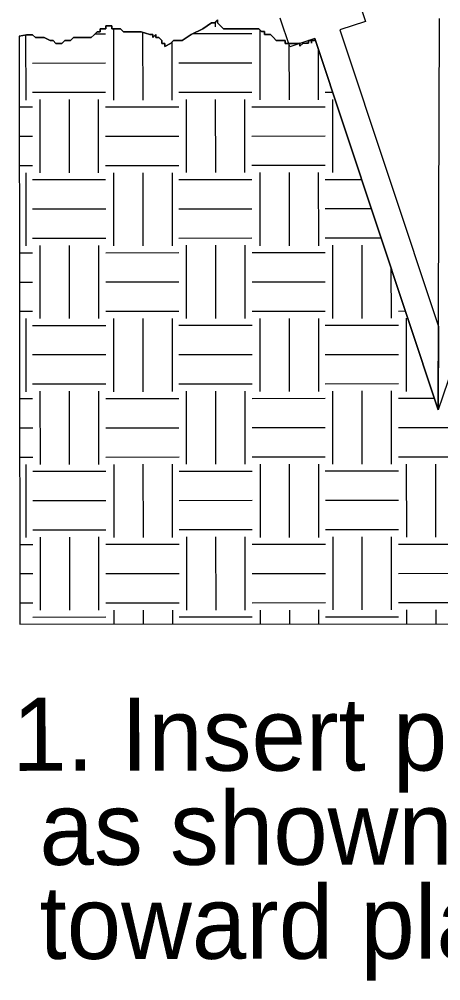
# Model space of a CAD drawing. Extents: x 1728110 to 1729925, y 1284214 to 1285339.
# Drawn here: x 1728642.1 to 1728681.8, y 1284892.4 to 1284982.9 of the extents above; entities that cross this region are included whole.
import ezdxf

# ---------------------------------------------------------------- set-up
doc = ezdxf.new("R2010")
doc.units = 0
doc.layers.add('Reforestation Detail CELL', color=7, linetype='Continuous')

msp = doc.modelspace()

# ---------------------------------------------------------------- linework, layer by layer
at = {"layer": 'Reforestation Detail CELL'}
for p, q in [((1728673.847, 1284985.427), (1728674.742, 1284982.732)), ((1728660.594, 1284982.672), (1728660.595, 1284982.231)), ((1728667.607, 1284980.362), (1728666.712, 1284983.056)), ((1728674.742, 1284982.732), (1728672.342, 1284981.935)), ((1728681.587, 1284946.157), (1728681.712, 1284983.026)), ((1728642.733, 1284981.47), (1728642.738, 1284975.328)), ((1728649.278, 1284981.582), (1728650.26, 1284981.582)), ((1728651, 1284982.048), (1728651.005, 1284975.334)), ((1728653.757, 1284981.727), (1728653.761, 1284975.336)), ((1728658.496, 1284981.589), (1728664.04, 1284981.592)), ((1728664.78, 1284981.962), (1728664.785, 1284975.345)), ((1728672.342, 1284981.935), (1728681.614, 1284954.007)), ((1728642.131, 1284981.35), (1728642.174, 1284925.976)), ((1728656.513, 1284980.797), (1728656.517, 1284975.338)), ((1728667.537, 1284980.677), (1728667.541, 1284975.346)), ((1728669.97, 1284981.148), (1728667.607, 1284980.362)), ((1728681.587, 1284946.157), (1728669.97, 1284981.148)), ((1728669.97, 1284981.148), (1728681.587, 1284946.157)), ((1728681.587, 1284946.157), (1728669.97, 1284981.148)), ((1728670.293, 1284980.178), (1728670.297, 1284975.348)), ((1728643.373, 1284978.821), (1728650.262, 1284978.826)), ((1728657.153, 1284978.831), (1728664.042, 1284978.837)), ((1728643.375, 1284976.065), (1728650.264, 1284976.07)), ((1728657.154, 1284976.075), (1728664.044, 1284976.081)), ((1728670.934, 1284976.086), (1728671.651, 1284976.087)), ((1728644.064, 1284975.377), (1728644.069, 1284968.487)), ((1728646.82, 1284975.379), (1728646.825, 1284968.49)), ((1728649.576, 1284975.381), (1728649.581, 1284968.491)), ((1728657.844, 1284975.387), (1728657.849, 1284968.498)), ((1728660.6, 1284975.389), (1728660.605, 1284968.5)), ((1728663.356, 1284975.391), (1728663.361, 1284968.501)), ((1728671.624, 1284975.397), (1728671.629, 1284968.508)), ((1728642.137, 1284974.687), (1728643.376, 1284974.688)), ((1728650.266, 1284974.693), (1728657.156, 1284974.698)), ((1728664.045, 1284974.703), (1728670.935, 1284974.708)), ((1728642.139, 1284971.931), (1728643.378, 1284971.932)), ((1728650.267, 1284971.937), (1728657.158, 1284971.942)), ((1728664.047, 1284971.947), (1728670.937, 1284971.952)), ((1728642.141, 1284969.175), (1728643.38, 1284969.176)), ((1728650.27, 1284969.181), (1728657.16, 1284969.186)), ((1728664.049, 1284969.191), (1728670.939, 1284969.196)), ((1728642.743, 1284968.486), (1728642.747, 1284961.596)), ((1728643.381, 1284967.846), (1728650.271, 1284967.851)), ((1728651.011, 1284968.493), (1728651.015, 1284961.602)), ((1728653.766, 1284968.495), (1728653.771, 1284961.604)), ((1728656.522, 1284968.496), (1728656.527, 1284961.607)), ((1728657.16, 1284967.856), (1728664.05, 1284967.861)), ((1728664.79, 1284968.503), (1728664.795, 1284961.613)), ((1728667.546, 1284968.505), (1728667.551, 1284961.615)), ((1728670.302, 1284968.506), (1728670.307, 1284961.617)), ((1728670.94, 1284967.866), (1728674.379, 1284967.869)), ((1728643.383, 1284965.09), (1728650.273, 1284965.095)), ((1728657.163, 1284965.1), (1728664.052, 1284965.105)), ((1728670.942, 1284965.11), (1728675.293, 1284965.114)), ((1728643.385, 1284962.334), (1728650.275, 1284962.339)), ((1728644.075, 1284961.646), (1728644.079, 1284954.756)), ((1728646.83, 1284961.648), (1728646.835, 1284954.758)), ((1728649.586, 1284961.65), (1728649.591, 1284954.76)), ((1728657.165, 1284962.344), (1728664.054, 1284962.349)), ((1728657.854, 1284961.656), (1728657.859, 1284954.766)), ((1728660.61, 1284961.658), (1728660.615, 1284954.769)), ((1728663.366, 1284961.66), (1728663.371, 1284954.77)), ((1728670.944, 1284962.354), (1728676.209, 1284962.358)), ((1728671.634, 1284961.666), (1728671.639, 1284954.777)), ((1728674.39, 1284961.668), (1728674.395, 1284954.779)), ((1728642.147, 1284960.955), (1728643.387, 1284960.956)), ((1728650.276, 1284960.962), (1728657.166, 1284960.967)), ((1728664.056, 1284960.972), (1728670.945, 1284960.977)), ((1728677.147, 1284959.532), (1728677.151, 1284954.78)), ((1728642.15, 1284958.2), (1728643.388, 1284958.201)), ((1728650.278, 1284958.206), (1728657.168, 1284958.211)), ((1728664.057, 1284958.216), (1728670.948, 1284958.221)), ((1728642.151, 1284955.444), (1728643.39, 1284955.445)), ((1728650.28, 1284955.45), (1728657.17, 1284955.455)), ((1728664.059, 1284955.46), (1728670.949, 1284955.465)), ((1728677.839, 1284955.47), (1728678.495, 1284955.471)), ((1728642.753, 1284954.755), (1728642.758, 1284947.865)), ((1728651.02, 1284954.761), (1728651.026, 1284947.871)), ((1728653.777, 1284954.764), (1728653.782, 1284947.873)), ((1728656.533, 1284954.765), (1728656.537, 1284947.875)), ((1728664.8, 1284954.772), (1728664.805, 1284947.881)), ((1728667.556, 1284954.774), (1728667.561, 1284947.883)), ((1728670.312, 1284954.775), (1728670.317, 1284947.886)), ((1728678.58, 1284954.782), (1728678.585, 1284947.891)), ((1728643.392, 1284954.115), (1728650.281, 1284954.12)), ((1728657.171, 1284954.125), (1728664.061, 1284954.13)), ((1728670.95, 1284954.135), (1728677.84, 1284954.14)), ((1728681.614, 1284954.007), (1728681.587, 1284946.157)), ((1728684.111, 1284953.591), (1728681.587, 1284946.157)), ((1728684.111, 1284953.591), (1728681.587, 1284946.157)), ((1728643.393, 1284951.359), (1728650.283, 1284951.364)), ((1728657.173, 1284951.369), (1728664.062, 1284951.374)), ((1728670.953, 1284951.379), (1728677.842, 1284951.384)), ((1728643.395, 1284948.603), (1728650.286, 1284948.608)), ((1728657.175, 1284948.613), (1728664.064, 1284948.618)), ((1728660.62, 1284947.927), (1728660.625, 1284941.037)), ((1728663.376, 1284947.929), (1728663.381, 1284941.039)), ((1728670.955, 1284948.623), (1728677.844, 1284948.628)), ((1728671.644, 1284947.935), (1728671.649, 1284941.045)), ((1728674.4, 1284947.937), (1728674.405, 1284941.048)), ((1728677.156, 1284947.939), (1728677.161, 1284941.049)), ((1728642.158, 1284947.223), (1728643.397, 1284947.224)), ((1728644.085, 1284947.914), (1728644.09, 1284941.025)), ((1728646.841, 1284947.917), (1728646.846, 1284941.027)), ((1728649.597, 1284947.919), (1728649.601, 1284941.028)), ((1728650.286, 1284947.23), (1728657.176, 1284947.235)), ((1728657.864, 1284947.925), (1728657.869, 1284941.035)), ((1728664.066, 1284947.241), (1728670.955, 1284947.246)), ((1728677.845, 1284947.251), (1728681.223, 1284947.253)), ((1728642.16, 1284944.468), (1728643.398, 1284944.469)), ((1728650.289, 1284944.473), (1728657.178, 1284944.48)), ((1728664.068, 1284944.485), (1728670.958, 1284944.49)), ((1728677.847, 1284944.495), (1728684.737, 1284944.5)), ((1728642.161, 1284941.712), (1728643.4, 1284941.713)), ((1728650.291, 1284941.719), (1728657.18, 1284941.724)), ((1728664.07, 1284941.729), (1728670.96, 1284941.734)), ((1728677.849, 1284941.739), (1728684.739, 1284941.744)), ((1728642.763, 1284941.023), (1728642.769, 1284934.134)), ((1728651.031, 1284941.03), (1728651.036, 1284934.14)), ((1728653.787, 1284941.032), (1728653.792, 1284934.142)), ((1728656.543, 1284941.034), (1728656.548, 1284934.144)), ((1728664.81, 1284941.04), (1728664.816, 1284934.15)), ((1728667.567, 1284941.042), (1728667.571, 1284934.152)), ((1728670.322, 1284941.044), (1728670.328, 1284934.155)), ((1728678.59, 1284941.051), (1728678.595, 1284934.16)), ((1728681.346, 1284941.053), (1728681.351, 1284934.162)), ((1728643.402, 1284940.384), (1728650.291, 1284940.389)), ((1728657.182, 1284940.394), (1728664.071, 1284940.399)), ((1728670.96, 1284940.404), (1728677.85, 1284940.409)), ((1728643.404, 1284937.628), (1728650.294, 1284937.633)), ((1728657.183, 1284937.638), (1728664.073, 1284937.643)), ((1728670.963, 1284937.648), (1728677.852, 1284937.653)), ((1728643.406, 1284934.872), (1728650.296, 1284934.877)), ((1728657.185, 1284934.882), (1728664.075, 1284934.887)), ((1728670.965, 1284934.892), (1728677.854, 1284934.897)), ((1728642.168, 1284933.492), (1728643.407, 1284933.493)), ((1728644.095, 1284934.183), (1728644.101, 1284927.293)), ((1728646.851, 1284934.185), (1728646.857, 1284927.295)), ((1728649.607, 1284934.188), (1728649.612, 1284927.297)), ((1728650.296, 1284933.499), (1728657.186, 1284933.503)), ((1728657.874, 1284934.193), (1728657.88, 1284927.304)), ((1728660.631, 1284934.196), (1728660.635, 1284927.306)), ((1728663.386, 1284934.198), (1728663.392, 1284927.308)), ((1728664.076, 1284933.509), (1728670.966, 1284933.514)), ((1728671.654, 1284934.204), (1728671.659, 1284927.314)), ((1728674.41, 1284934.206), (1728674.415, 1284927.316)), ((1728677.166, 1284934.208), (1728677.171, 1284927.318)), ((1728677.856, 1284933.52), (1728684.745, 1284933.525)), ((1728642.17, 1284930.737), (1728643.409, 1284930.738)), ((1728650.299, 1284930.742), (1728657.188, 1284930.748)), ((1728664.078, 1284930.754), (1728670.968, 1284930.759)), ((1728677.857, 1284930.764), (1728684.748, 1284930.769)), ((1728677.859, 1284928.008), (1728684.75, 1284928.013)), ((1728642.172, 1284927.981), (1728643.41, 1284927.982)), ((1728650.301, 1284927.987), (1728657.19, 1284927.992)), ((1728651.041, 1284927.299), (1728651.043, 1284925.982)), ((1728653.797, 1284927.3), (1728653.799, 1284925.985)), ((1728656.553, 1284927.302), (1728656.554, 1284925.987)), ((1728664.081, 1284927.998), (1728670.97, 1284928.003)), ((1728664.821, 1284927.309), (1728664.822, 1284925.993)), ((1728667.576, 1284927.31), (1728667.577, 1284925.995)), ((1728670.333, 1284927.313), (1728670.333, 1284925.997)), ((1728678.6, 1284927.319), (1728678.601, 1284926.003)), ((1728681.356, 1284927.321), (1728681.357, 1284926.005)), ((1728643.412, 1284926.652), (1728650.301, 1284926.657)), ((1728657.192, 1284926.663), (1728664.081, 1284926.668)), ((1728670.971, 1284926.673), (1728677.861, 1284926.678)), ((1728642.174, 1284925.976), (1728724.077, 1284926.037))]:
    msp.add_line(p, q, dxfattribs=at)
for points in [[(1728642.131, 1284981.35), (1728642.825, 1284981.488), (1728643.1, 1284981.489), (1728643.378, 1284981.489), (1728643.654, 1284981.212), (1728643.931, 1284981.212), (1728644.208, 1284981.213), (1728644.485, 1284981.213), (1728645.038, 1284980.936), (1728645.315, 1284980.935), (1728645.592, 1284980.661), (1728645.869, 1284980.661), (1728646.145, 1284980.661), (1728646.422, 1284980.937), (1728646.698, 1284980.937), (1728646.976, 1284980.937), (1728647.252, 1284981.215), (1728647.529, 1284981.215), (1728647.805, 1284981.215), (1728648.082, 1284981.215), (1728648.358, 1284981.216), (1728648.635, 1284981.216), (1728648.912, 1284981.216), (1728649.189, 1284981.493), (1728649.466, 1284981.769), (1728649.742, 1284981.77), (1728649.742, 1284982.047), (1728650.018, 1284982.048), (1728650.295, 1284982.048), (1728650.294, 1284982.324), (1728650.571, 1284982.325), (1728650.849, 1284982.325), (1728650.849, 1284982.048), (1728651.124, 1284982.048), (1728651.402, 1284982.049), (1728651.678, 1284982.049), (1728651.956, 1284981.771), (1728652.232, 1284981.772), (1728652.508, 1284981.772), (1728652.785, 1284981.773), (1728653.063, 1284981.773), (1728653.338, 1284981.772), (1728653.615, 1284981.773), (1728654.446, 1284981.497), (1728654.722, 1284981.497), (1728654.723, 1284981.22), (1728654.999, 1284981.497), (1728654.999, 1284981.221), (1728655.276, 1284981.221), (1728655.554, 1284980.944), (1728655.553, 1284980.668), (1728655.83, 1284980.668), (1728655.553, 1284980.668), (1728655.83, 1284980.668), (1728655.831, 1284980.39), (1728656.383, 1284980.669), (1728656.66, 1284980.944), (1728656.936, 1284980.945), (1728657.489, 1284980.945), (1728658.32, 1284981.5), (1728659.426, 1284982.055), (1728660.256, 1284982.609), (1728660.532, 1284982.61), (1728660.809, 1284982.886), (1728660.809, 1284982.61), (1728661.086, 1284982.332), (1728661.363, 1284982.056), (1728661.64, 1284982.056), (1728661.915, 1284982.056), (1728662.47, 1284982.056), (1728662.746, 1284982.057), (1728663.023, 1284982.057), (1728663.576, 1284982.058), (1728663.854, 1284982.058), (1728664.13, 1284982.058), (1728664.684, 1284982.058), (1728664.96, 1284981.781), (1728665.237, 1284981.782), (1728665.237, 1284981.505), (1728665.513, 1284981.505), (1728665.792, 1284981.506), (1728666.068, 1284981.229), (1728666.345, 1284980.952), (1728666.621, 1284980.952), (1728666.897, 1284980.952), (1728667.175, 1284980.952), (1728667.174, 1284980.677), (1728667.452, 1284980.677), (1728667.728, 1284980.677), (1728668.005, 1284980.677), (1728668.281, 1284980.677), (1728668.558, 1284980.678), (1728668.559, 1284980.4), (1728668.835, 1284980.677), (1728669.112, 1284980.678), (1728669.388, 1284980.678), (1728669.388, 1284980.953), (1728669.665, 1284980.954), (1728669.664, 1284980.679), (1728669.665, 1284980.954), (1728669.941, 1284980.954)], [(1728669.941, 1284980.954), (1728669.665, 1284980.954), (1728669.664, 1284980.679), (1728669.665, 1284980.954), (1728669.388, 1284980.953), (1728669.388, 1284980.678), (1728669.112, 1284980.678), (1728668.835, 1284980.677), (1728668.559, 1284980.4), (1728668.558, 1284980.678), (1728668.281, 1284980.677), (1728668.005, 1284980.677), (1728667.728, 1284980.677), (1728667.452, 1284980.677), (1728667.174, 1284980.677), (1728667.175, 1284980.952), (1728666.897, 1284980.952), (1728666.621, 1284980.952), (1728666.345, 1284980.952), (1728666.068, 1284981.229), (1728665.792, 1284981.506), (1728665.513, 1284981.505), (1728665.237, 1284981.505), (1728665.237, 1284981.782), (1728664.96, 1284981.781), (1728664.684, 1284982.058), (1728664.13, 1284982.058), (1728663.854, 1284982.058), (1728663.576, 1284982.058), (1728663.023, 1284982.057), (1728662.746, 1284982.057), (1728662.47, 1284982.056), (1728661.915, 1284982.056), (1728661.64, 1284982.056), (1728661.363, 1284982.056), (1728661.086, 1284982.332), (1728660.809, 1284982.61), (1728660.809, 1284982.886), (1728660.532, 1284982.61), (1728660.256, 1284982.609), (1728659.426, 1284982.055), (1728658.32, 1284981.5), (1728657.489, 1284980.945), (1728656.936, 1284980.945), (1728656.66, 1284980.944), (1728656.383, 1284980.669), (1728655.831, 1284980.39), (1728655.83, 1284980.668), (1728655.553, 1284980.668), (1728655.83, 1284980.668), (1728655.553, 1284980.668), (1728655.554, 1284980.944), (1728655.276, 1284981.221), (1728654.999, 1284981.221), (1728654.999, 1284981.497), (1728654.723, 1284981.22), (1728654.722, 1284981.497), (1728654.446, 1284981.497), (1728653.615, 1284981.773), (1728653.338, 1284981.772), (1728653.063, 1284981.773), (1728652.785, 1284981.773), (1728652.508, 1284981.772), (1728652.232, 1284981.772), (1728651.956, 1284981.771), (1728651.678, 1284982.049), (1728651.402, 1284982.049), (1728651.124, 1284982.048), (1728650.849, 1284982.048), (1728650.849, 1284982.325), (1728650.571, 1284982.325), (1728650.294, 1284982.324), (1728650.295, 1284982.048), (1728650.018, 1284982.048), (1728649.742, 1284982.047), (1728649.742, 1284981.77), (1728649.466, 1284981.769), (1728649.189, 1284981.493), (1728648.912, 1284981.216), (1728648.635, 1284981.216), (1728648.358, 1284981.216), (1728648.082, 1284981.215), (1728647.805, 1284981.215), (1728647.529, 1284981.215), (1728647.252, 1284981.215), (1728646.976, 1284980.937), (1728646.698, 1284980.937), (1728646.422, 1284980.937), (1728646.145, 1284980.661), (1728645.869, 1284980.661), (1728645.592, 1284980.661), (1728645.315, 1284980.935), (1728645.038, 1284980.936), (1728644.485, 1284981.213), (1728644.208, 1284981.213), (1728643.931, 1284981.212), (1728643.654, 1284981.212), (1728643.378, 1284981.489), (1728643.1, 1284981.489), (1728642.825, 1284981.488), (1728642.131, 1284981.35)]]:
    msp.add_lwpolyline(points, dxfattribs=at)

# ---------------------------------------------------------------- texts
for s, p in [('1. Insert planting bar ', (1728641.478, 1284912.165)), (' as shown and pull handle ', (1728641.484, 1284903.307)), (' toward planter.', (1728641.491, 1284894.449))]:
    msp.add_text(s, height=6.88975, rotation=0.04293, dxfattribs=at).set_placement(p)

doc.saveas('drawing.dxf')
